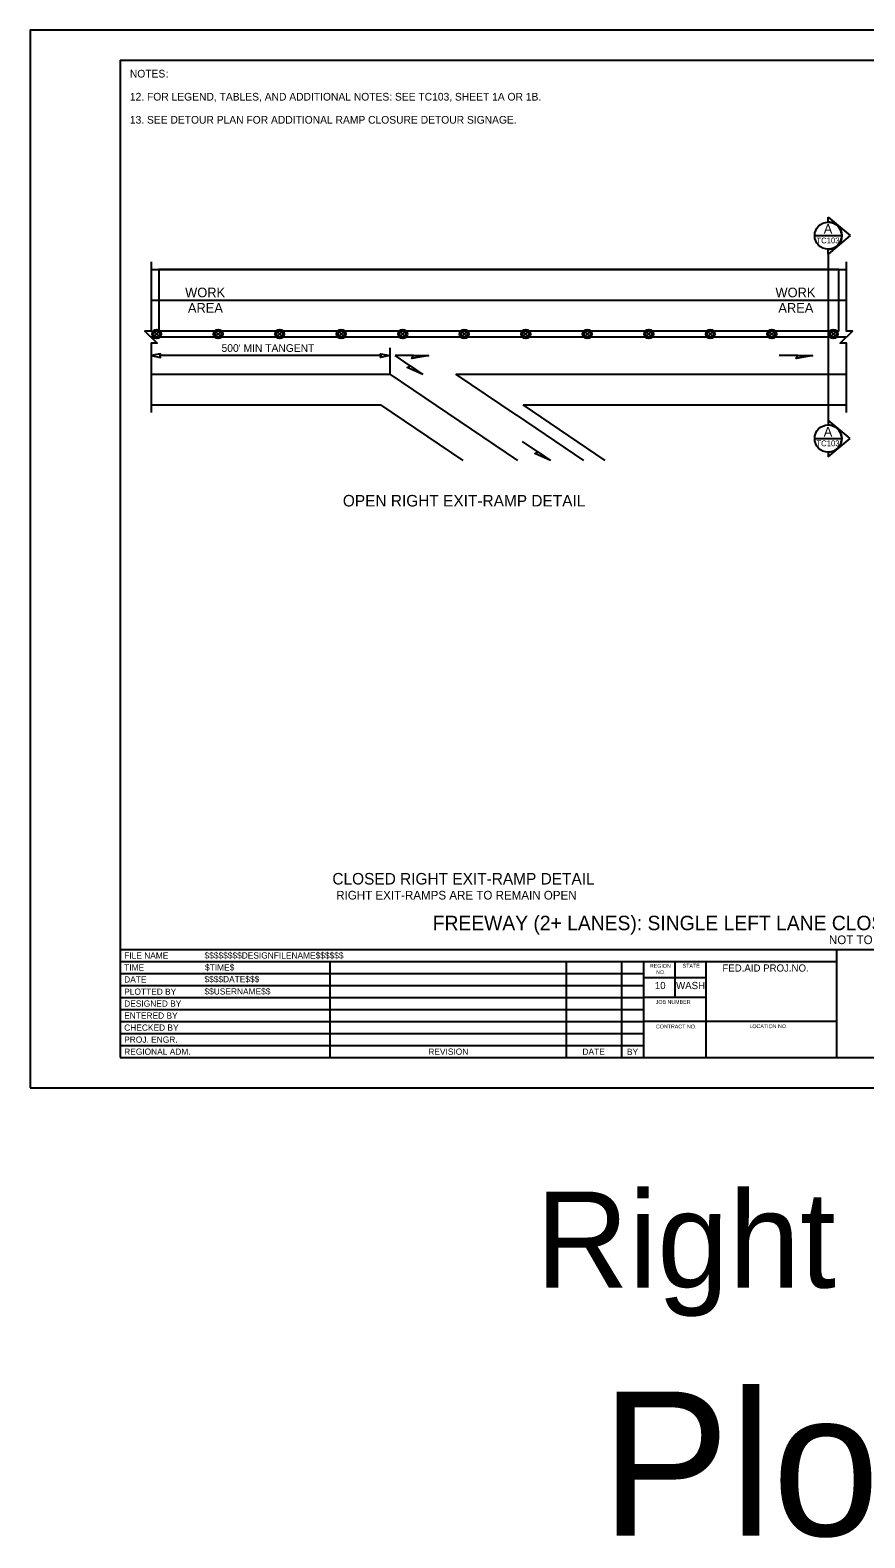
# Model space of a CAD drawing. Extents: x 99999 to 100116, y 99995 to 100013.
# Drawn here: x 100039.06 to 100047.75, y 99995.01 to 100010.69 of the extents above; entities that cross this region are included whole.
import ezdxf

# ---------------------------------------------------------------- set-up
doc = ezdxf.new("R2010")
doc.units = 0
for name, color, linetype in [('RD_MK_LineEdgeYellow', 7, 'Continuous'), ('RD_MK_LineLane', 7, 'Continuous'), ('SH_DE_DetailHeading1Text', 7, 'Continuous'), ('SH_DE_DetailHeading2Text', 7, 'Continuous'), ('SH_GI_GeneralNotesBodyText', 7, 'Continuous'), ('SH_GI_PlotLimits', 7, 'Continuous'), ('SH_GI_SheetBorder', 7, 'Continuous'), ('SH_GI_SheetLocationText', 7, 'Continuous'), ('SH_GI_SheetTextInCells', 7, 'Continuous'), ('SH_GI_TitleBlockText', 7, 'Continuous'), ('SH_TI_WZSectionCut', 7, 'Continuous'), ('TR_WZ_TrafficSafetyDrum', 7, 'Continuous'), ('TR_WZ_WorkAreaLabel', 7, 'Continuous'), ('TR_WZ_WorkZoneDetails', 7, 'Continuous'), ('TR_WZ_WorkZoneTextCurrent', 7, 'Continuous')]:
    doc.layers.add(name, color=color, linetype=linetype)

msp = doc.modelspace()

# ---------------------------------------------------------------- linework, layer by layer
at = {"layer": 'RD_MK_LineEdgeYellow'}
for p, q in [((100040.32, 100007.879), (100047.555, 100007.879)), ((100040.32, 100007.111), (100042.806, 100007.111)), ((100042.806, 100007.111), (100044.133, 100006.211)), ((100044.191, 100007.111), (100047.555, 100007.111)), ((100044.119, 100006.685), (100044.818, 100006.211))]:
    msp.add_line(p, q, dxfattribs=at)
at = {"layer": 'RD_MK_LineLane'}
msp.add_lwpolyline([(100047.555, 100007.495), (100040.32, 100007.495)], dxfattribs=at)
at = {"layer": 'SH_GI_PlotLimits'}
msp.add_lwpolyline([(100039.062, 99999.687), (100056.062, 99999.687), (100056.062, 100010.687), (100039.062, 100010.687)], close=True, dxfattribs=at)
at = {"layer": 'SH_GI_SheetBorder'}
for p, q in [((100040, 100010.375), (100040, 100000)), ((100040, 100010.375), (100055.75, 100010.375)), ((100040, 100001.126), (100055.75, 100001.126)), ((100047.457, 100000), (100047.457, 100001.126)), ((100040, 100001.001), (100047.457, 100001.001)), ((100042.179, 100001.001), (100042.179, 100000)), ((100044.641, 100001.001), (100044.641, 100000)), ((100045.216, 100001.001), (100045.216, 100000)), ((100045.445, 100001.001), (100045.445, 100000)), ((100045.772, 100000.625), (100045.772, 100001.001)), ((100046.096, 100000), (100046.096, 100001.001)), ((100040, 100000.876), (100042.182, 100000.876)), ((100042.182, 100000.876), (100045.447, 100000.876)), ((100046.096, 100000.831), (100045.447, 100000.831)), ((100040, 100000.751), (100042.182, 100000.751)), ((100040, 100000.625), (100045.447, 100000.625)), ((100042.182, 100000.751), (100045.447, 100000.751)), ((100046.096, 100000.625), (100045.447, 100000.625)), ((100040, 100000.5), (100045.447, 100000.5)), ((100040, 100000.375), (100045.447, 100000.375)), ((100047.457, 100000.375), (100045.447, 100000.375)), ((100040, 100000.25), (100045.447, 100000.25)), ((100040, 100000.125), (100045.447, 100000.125)), ((100040, 100000), (100055.75, 100000))]:
    msp.add_line(p, q, dxfattribs=at)
at = {"layer": 'SH_TI_WZSectionCut'}
for p, q in [((100047.366, 100008.691), (100047.366, 100008.741)), ((100047.366, 100008.741), (100047.594, 100008.55)), ((100047.594, 100008.55), (100047.366, 100008.359)), ((100047.366, 100008.359), (100047.366, 100008.409)), ((100047.366, 100008.359), (100047.366, 100006.631)), ((100047.366, 100006.631), (100047.366, 100006.581)), ((100047.594, 100006.44), (100047.366, 100006.631)), ((100047.366, 100006.249), (100047.594, 100006.44)), ((100047.366, 100006.299), (100047.366, 100006.249))]:
    msp.add_line(p, q, dxfattribs=at)
for points in [[(100047.224, 100008.55), (100047.507, 100008.55)], [(100047.224, 100006.44), (100047.507, 100006.44)]]:
    msp.add_lwpolyline(points, dxfattribs=at)
for centre in [(100047.366, 100008.55), (100047.366, 100006.44)]:
    msp.add_circle(centre, 0.141, dxfattribs=at)
for centre in [(100047.366, 100008.55), (100047.366, 100006.44)]:
    msp.add_arc(centre, 0.141, 269.9978, 90.0022, dxfattribs=at)
at = {"layer": 'TR_WZ_TrafficSafetyDrum'}
for p, q in [((100040.356, 100007.504), (100040.402, 100007.55)), ((100040.402, 100007.504), (100040.356, 100007.55)), ((100040.996, 100007.504), (100041.042, 100007.55)), ((100041.042, 100007.504), (100040.996, 100007.55)), ((100041.636, 100007.504), (100041.682, 100007.55)), ((100041.682, 100007.504), (100041.636, 100007.55)), ((100042.276, 100007.504), (100042.322, 100007.55)), ((100042.322, 100007.504), (100042.276, 100007.55)), ((100042.916, 100007.504), (100042.962, 100007.55)), ((100042.962, 100007.504), (100042.916, 100007.55)), ((100043.556, 100007.504), (100043.602, 100007.55)), ((100043.602, 100007.504), (100043.556, 100007.55)), ((100044.196, 100007.504), (100044.242, 100007.55)), ((100044.242, 100007.504), (100044.196, 100007.55)), ((100044.836, 100007.504), (100044.882, 100007.55)), ((100044.882, 100007.504), (100044.836, 100007.55)), ((100045.476, 100007.504), (100045.522, 100007.55)), ((100045.522, 100007.504), (100045.476, 100007.55)), ((100046.116, 100007.504), (100046.162, 100007.55)), ((100046.162, 100007.504), (100046.116, 100007.55)), ((100046.756, 100007.504), (100046.802, 100007.55)), ((100046.802, 100007.504), (100046.756, 100007.55)), ((100047.396, 100007.504), (100047.442, 100007.55)), ((100047.442, 100007.504), (100047.396, 100007.55))]:
    msp.add_line(p, q, dxfattribs=at)
for centre, radius in [((100040.379, 100007.527), 0.048), ((100040.379, 100007.527), 0.048), ((100040.379, 100007.527), 0.032), ((100041.019, 100007.527), 0.048), ((100041.019, 100007.527), 0.048), ((100041.019, 100007.527), 0.032), ((100041.659, 100007.527), 0.048), ((100041.659, 100007.527), 0.048), ((100041.659, 100007.527), 0.032), ((100042.299, 100007.527), 0.048), ((100042.299, 100007.527), 0.048), ((100042.299, 100007.527), 0.032), ((100042.939, 100007.527), 0.048), ((100042.939, 100007.527), 0.048), ((100042.939, 100007.527), 0.032), ((100043.579, 100007.527), 0.048), ((100043.579, 100007.527), 0.048), ((100043.579, 100007.527), 0.032), ((100044.219, 100007.527), 0.048), ((100044.219, 100007.527), 0.048), ((100044.219, 100007.527), 0.032), ((100044.859, 100007.527), 0.048), ((100044.859, 100007.527), 0.048), ((100044.859, 100007.527), 0.032), ((100045.499, 100007.527), 0.048), ((100045.499, 100007.527), 0.048), ((100045.499, 100007.527), 0.032), ((100046.139, 100007.527), 0.048), ((100046.139, 100007.527), 0.048), ((100046.139, 100007.527), 0.032), ((100046.779, 100007.527), 0.048), ((100046.779, 100007.527), 0.048), ((100046.779, 100007.527), 0.032), ((100047.419, 100007.527), 0.048), ((100047.419, 100007.527), 0.048), ((100047.419, 100007.527), 0.032)]:
    msp.add_circle(centre, radius, dxfattribs=at)
at = {"layer": 'TR_WZ_WorkZoneDetails'}
for p, q in [((100040.32, 100008.199), (100047.555, 100008.199)), ((100042.806, 100007.383), (100042.806, 100007.111)), ((100042.713, 100007.303), (100040.414, 100007.303)), ((100043.018, 100007.195), (100042.859, 100007.303)), ((100043.052, 100007.303), (100042.859, 100007.303)), ((100047.049, 100007.303), (100046.856, 100007.303)), ((100043.491, 100007.111), (100044.191, 100007.111)), ((100044.119, 100006.685), (100043.491, 100007.111)), ((100040.32, 100006.791), (100042.708, 100006.791)), ((100042.708, 100006.791), (100043.563, 100006.211)), ((100044.191, 100006.791), (100047.555, 100006.791)), ((100045.045, 100006.211), (100044.191, 100006.791)), ((100044.345, 100006.3), (100044.186, 100006.408))]:
    msp.add_line(p, q, dxfattribs=at)
for points in [[(100040.32, 100008.279), (100040.32, 100007.557), (100040.256, 100007.557), (100040.384, 100007.433), (100040.32, 100007.433), (100040.32, 100006.711)], [(100047.555, 100006.711), (100047.555, 100007.433), (100047.491, 100007.433), (100047.619, 100007.557), (100047.555, 100007.557), (100047.555, 100008.279)]]:
    msp.add_lwpolyline(points, dxfattribs=at)
for points in [[(100040.4, 100008.199), (100040.4, 100007.559), (100047.475, 100007.559), (100047.475, 100008.199)], [(100040.32, 100007.303), (100040.418, 100007.284), (100040.414, 100007.303), (100040.418, 100007.322)], [(100042.806, 100007.303), (100042.708, 100007.284), (100042.713, 100007.303), (100042.708, 100007.322)], [(100043.209, 100007.303), (100043.034, 100007.272), (100043.052, 100007.303)], [(100047.206, 100007.303), (100047.031, 100007.272), (100047.049, 100007.303)], [(100043.149, 100007.106), (100042.986, 100007.179), (100043.018, 100007.195)], [(100044.476, 100006.211), (100044.313, 100006.284), (100044.345, 100006.3)]]:
    msp.add_lwpolyline(points, close=True, dxfattribs=at)

# ---------------------------------------------------------------- texts
at = {"layer": 'SH_DE_DetailHeading1Text'}
for s, height, p in [('FREEWAY (2+ LANES): SINGLE LEFT LANE CLOSURE (MAINTAIN EXISTING SPEED LIMIT)', 0.15, (100043.251, 100001.326)), ('NOT TO SCALE', 0.09, (100047.373, 100001.181))]:
    msp.add_text(s, height=height, rotation=360, dxfattribs=at).set_placement(p)
at = {"layer": 'SH_DE_DetailHeading2Text'}
for s, height, p in [('OPEN RIGHT EXIT-RAMP DETAIL', 0.12, (100042.316, 100005.733)), ('CLOSED RIGHT EXIT-RAMP DETAIL', 0.12, (100042.207, 100001.801)), ('RIGHT EXIT-RAMPS ARE TO REMAIN OPEN', 0.09, (100042.247, 100001.645))]:
    msp.add_text(s, height=height, rotation=360, dxfattribs=at).set_placement(p)
at = {"layer": 'SH_GI_GeneralNotesBodyText'}
for s, p in [('NOTES', (100040.1, 100010.195)), (':', (100040.474, 100010.195)), ('12. FOR LEGEND, TABLES, AND ADDITIONAL NOTES: SEE TC103, SHEET 1A OR 1B.', (100040.1, 100009.955)), ('13. SEE DETOUR PLAN FOR ADDITIONAL RAMP CLOSURE DETOUR SIGNAGE.', (100040.1, 100009.715))]:
    msp.add_text(s, height=0.08, rotation=360, dxfattribs=at).set_placement(p)
at = {"layer": 'SH_GI_SheetLocationText'}
for s, height, p in [('Right Ramps', 1, (100044.324, 99997.607)), ('Plot 3', 1.5, (100045.001, 99995.027))]:
    msp.add_text(s, height=height, dxfattribs=at).set_placement(p)
at = {"layer": 'SH_GI_SheetTextInCells'}
for s, height, p in [('FILE NAME', 0.0651, (100040.041, 100001.031)), ('TIME', 0.0651, (100040.041, 100000.906)), ('REGION', 0.04, (100045.51, 100000.935)), ('STATE', 0.04, (100045.851, 100000.936)), ('FED.AID PROJ.NO.', 0.07506, (100046.265, 100000.895)), ('DATE', 0.0651, (100040.041, 100000.781)), ('10', 0.0751, (100045.562, 100000.713)), ('NO.', 0.04, (100045.575, 100000.869)), ('WASH', 0.0751, (100045.783, 100000.713)), ('PLOTTED BY', 0.0651, (100040.041, 100000.654)), ('DESIGNED BY', 0.06505, (100040.041, 100000.53)), ('ENTERED BY', 0.0651, (100040.041, 100000.405)), ('JOB NUMBER', 0.04, (100045.571, 100000.559)), ('CHECKED BY', 0.0651, (100040.041, 100000.28)), ('CONTRACT NO.', 0.04003, (100045.573, 100000.304)), ('LOCATION NO.', 0.04003, (100046.546, 100000.307)), ('PROJ. ENGR.', 0.06505, (100040.041, 100000.155)), ('REGIONAL ADM.', 0.06505, (100040.041, 100000.03)), ('REVISION', 0.0651, (100043.205, 100000.03)), ('DATE', 0.0651, (100044.809, 100000.03)), ('BY', 0.0651, (100045.272, 100000.028))]:
    msp.add_text(s, height=height, dxfattribs=at).set_placement(p)
at = {"layer": 'SH_GI_TitleBlockText'}
for s, height, p in [('$$$$$$$$DESIGNFILENAME$$$$$$', 0.06505, (100040.877, 100001.031)), ('$TIME$', 0.0651, (100040.882, 100000.906)), ('$$$$DATE$$$', 0.06505, (100040.876, 100000.784)), ('$$USERNAME$$', 0.06505, (100040.876, 100000.657))]:
    msp.add_text(s, height=height, dxfattribs=at).set_placement(p)
at = {"layer": 'SH_TI_WZSectionCut'}
for s, height, rotation, p in [('A', 0.1, 0.01, (100047.319, 100008.571)), ('TC103', 0.06, 360, (100047.243, 100008.47)), ('A', 0.1, 0.01, (100047.319, 100006.46)), ('TC103', 0.06, 360, (100047.243, 100006.36))]:
    msp.add_text(s, height=height, rotation=rotation, dxfattribs=at).set_placement(p)
at = {"layer": 'TR_WZ_WorkAreaLabel'}
for s, p in [('WORK', (100040.675, 100007.909)), ('WORK', (100046.817, 100007.909)), ('AREA', (100040.704, 100007.749)), ('AREA', (100046.847, 100007.749))]:
    msp.add_text(s, height=0.1, dxfattribs=at).set_placement(p)
at = {"layer": 'TR_WZ_WorkZoneTextCurrent'}
msp.add_text("500' MIN TANGENT", height=0.08, dxfattribs=at).set_placement((100041.054, 100007.341))

doc.saveas('drawing.dxf')
